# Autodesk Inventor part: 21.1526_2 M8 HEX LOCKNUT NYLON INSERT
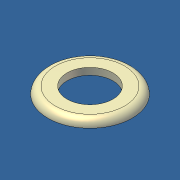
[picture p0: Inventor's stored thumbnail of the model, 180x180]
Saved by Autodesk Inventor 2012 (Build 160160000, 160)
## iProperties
Created: 2014-10
Part Number: 21.1526_2 M8 HEX LOCKNUT NYLON INSERT
Material: Nylon-6/6
Document SubType Name: Modeling
Designer: Admin
Density: 1.13 g/cm^3
Mass: 0.0898009 g
Surface Area: 2.17076 cm^2
Volume: 0.0794699 cm^3
Author: Admin
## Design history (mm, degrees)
feature "Base1"
body "Solid1"
